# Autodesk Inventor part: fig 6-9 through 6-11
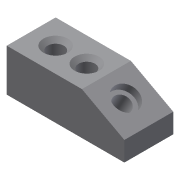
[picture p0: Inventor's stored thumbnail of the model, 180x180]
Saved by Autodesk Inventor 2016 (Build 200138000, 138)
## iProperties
Created: 2009-09
Part Number: fig 6-9 through 6-11
Document SubType Name: Modeling
Designer: Sham
Density: 1 g/cm^3
Material: Generic
Appearance: Default
Author: Sham
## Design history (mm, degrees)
sketch "Sketch1"
  geometry: L1 (-40, 0)-(-40, 12); L2 (-40, 12)-(-14, 26); L3 (-14, 26)-(32.108, 26); L4 (-40, 0)-(32.108, 0); L5 (32.108, 0)-(32.108, 26)
  constraints: 10 end point, 3 perpendicular
extrude "Extrusion1" new body sketch "Sketch1" distance "d0" = 30; taper "d1" = 0 deg
hole "Hole1" diameter "d4" = 10; stored, may be unused: countersink angle "d8" = 90 deg, drill point angle "d10" = 118 deg; dims "d2" = 15, "d3" = 16, "d5" = 6, "d6" = 15, "d7" = 5, "d9" = 12
hole "Hole2" diameter "d13" = 10; stored, may be unused: countersink angle "d17" = 90 deg, drill point angle "d19" = 118 deg; dims "d11" = 12, "d12" = 15, "d14" = 6, "d15" = 15, "d16" = 2, "d18" = 15
hole "Hole3" diameter "d22" = 10; stored, may be unused: countersink angle "d26" = 90 deg, drill point angle "d28" = 118 deg; dims "d20" = 15, "d21" = 15, "d23" = 6, "d24" = 15, "d25" = 2, "d27" = 15
body "Solid1"
